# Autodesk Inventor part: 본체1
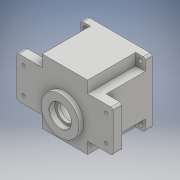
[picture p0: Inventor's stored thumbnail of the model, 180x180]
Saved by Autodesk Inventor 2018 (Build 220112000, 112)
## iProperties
Created: 2020-07
Part Number: 본체1
Material: 일반
Document SubType Name: Modeling
Designer: Admin
Density: 1 g/cm^3
Appearance: 기본값
Author: Admin
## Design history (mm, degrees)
sketch "스케치1"
  geometry: L1 (0, -65.8)-(0, 65.8) reference; L2 (-98, 0)-(98, 0) reference; L3 (33, 47)-(-33, 47); L4 (-33, 47)-(-33, 30); L5 (-33, 30)-(-70, 30); L6 (-70, 30)-(-70, -30); L7 (-70, -30)-(-33, -30); L8 (-33, -30)-(-33, -47); L9 (-33, -47)-(33, -47); L10 (33, -47)-(33, -30); L11 (33, -30)-(70, -30); L12 (70, -30)-(70, 30); L13 (70, 30)-(33, 30); L14 (33, 47)-(33, 30); 1 further point
  constraints: 24 end point, 8 perpendicular, 7 point on line, 1 horizontal, 3 other
  dimensions: "d0" = 140 distance between parallel lines of L6 L12; "d1" = 60 distance between parallel lines of L7 L5; "d2" = 66 distance of L3.start L3.end; "d3" = 17 distance of L3.end L4.end; "d4" = 17 distance of L7.end L8.end
extrude "돌출1" new body sketch "스케치1" distance "d5" = 13; taper "d6" = 0 deg
sketch "스케치2"
  geometry: L1 (-33, -47)-(33, -47) reference; L2 (33, -47)-(33, -30) reference; L3 (33, -30)-(70, -30) reference; L4 (70, -30)-(70, 30) reference; L5 (70, 30)-(33, 30) reference; L6 (33, 30)-(33, 47) reference; L7 (33, 47)-(-33, 47) reference; L8 (-33, 47)-(-33, 30) reference; L9 (-33, 30)-(-70, 30) reference; L10 (-70, 30)-(-70, -30) reference; L11 (-70, -30)-(-33, -30) reference; L12 (-33, -30)-(-33, -47) reference; L13 (-47, -47)-(47, -47); L14 (47, -47)-(47, 47); L15 (47, 47)-(-47, 47); L16 (-47, 47)-(-47, -47); L17 (-47, -47)-(47, 47); L18 (47, -47)-(-47, 47); 1 further point
  constraints: 12 end point, 2 midpoint, 2 parallel, 1 horizontal, 1 perpendicular
  dimensions: "d7" = 94 distance of L14.end L15.end; "d8" = 94 distance of L13.end L14.end
extrude "돌출2" join sketch "스케치2" distance "d9" = 67; taper "d10" = 0 deg
sketch "스케치3"
  geometry: L1 (-33, 47)-(33, 47) reference; L2 (-33, 30)-(-33, 47) reference; L3 (-70, 30)-(-33, 30) reference; L4 (-70, -30)-(-70, 30) reference; L5 (-33, -30)-(-70, -30) reference; L6 (-33, -47)-(-33, -30) reference; L7 (33, -47)-(-33, -47) reference; L8 (33, -30)-(33, -47) reference; L9 (70, -30)-(33, -30) reference; L10 (70, 30)-(70, -30) reference; L11 (33, 30)-(70, 30) reference; L12 (33, 47)-(33, 30) reference; L13 (33, 47)-(47, 47) reference; L14 (47, 47)-(47, 30) reference; L15 (47, -30)-(47, -47) reference; L16 (47, -47)-(33, -47) reference; L17 (-33, -47)-(-47, -47) reference; L18 (-47, -47)-(-47, -30) reference; L19 (-47, 30)-(-47, 47) reference; L20 (-47, 47)-(-33, 47) reference; L21 (47, -47)-(-47, -47) reference; L22 (-47, -47)-(-33, -47); L23 (-33, -47)-(-33, -30); L24 (-33, -30)-(-47, -30); L25 (-47, -30)-(-47, -47); L26 (-47, 30)-(-33, 30) reference; L27 (-47, 30)-(-33, 30); L28 (-33, 30)-(-33, 47); L29 (-33, 47)-(-47, 47); L30 (-47, 47)-(-47, 30); L31 (33, 47)-(33, 30) reference; L32 (33, 30)-(47, 30); L33 (47, 30)-(47, 47); L34 (47, 47)-(33, 47); L35 (33, 47)-(33, 30); L36 (33, -47)-(-33, -47) reference; L37 (33, -47)-(47, -47); L38 (47, -47)-(47, -30); L39 (47, -30)-(33, -30); L40 (33, -30)-(33, -47); 1 further point
  constraints: 32 end point, 8 parallel, 4 horizontal, 4 perpendicular
extrude "돌출3" cut sketch "스케치3" distance "d11" = 70; taper "d12" = 0 deg
sketch "스케치8"
  geometry: L1 (98, 0)-(-98, 0) reference; L2 (0, 65.8)-(0, -65.8) reference; C1 r 43 at (0, 0); 1 further point
  constraints: 1 centre point, 1 coincident
  dimensions: "d28" = 86 diameter of C1
extrude "돌출8" cut sketch "스케치8" distance "d29" = 9; taper "d30" = 0 deg
sketch "스케치9"
  geometry: C1 r 43 at (0, 0) reference; C2 r 40 at (0, 0); 1 further point
  constraints: 1 centre point, 1 coincident
  dimensions: "d31" = 80 diameter of C2
extrude "돌출9" cut sketch "스케치9" distance "d32" = 55; taper "d33" = 0 deg
sketch "스케치13"
  geometry: L1 (0, 65.8)-(0, -65.8) reference; L2 (98, 0)-(-98, 0) reference; L3 (-35.778, 3.994)-(-39.8, 3.994); L4 (-35.778, -3.994)-(-39.8, -3.994); C1 r 40 at (0, 0) reference; C2 r 43 at (0, 0) reference; A1 r 40 centre (0, 0) between (-39.8, 3.994) and (-39.8, -3.994) reference; A2 r 36 centre (0, 0) between (-36, 0) and (-35.778, 3.994); A3 r 4 centre (-36, 0) between (-36.222, -3.994) and (-36.222, 3.994); A4 r 40 centre (0, 0) between (-39.8, 3.994) and (-39.8, -3.994); 1 further point
  constraints: 11 point on circle, 4 end point, 3 centre point, 3 point on line, 2 coincident, 2 horizontal
  dimensions: "d45" = 72 diameter of A2; "d46" = 8 diameter of A3
extrude "돌출13" join sketch "스케치13" stored distance "d47" = 7; taper "d48" = 0 deg
sketch "스케치14"
  geometry: L1 (0, 65.8)-(0, -65.8) reference; L2 (98, 0)-(-98, 0) reference; L3 (-35.778, 3.994)-(-39.8, 3.994) reference; L4 (-39.8, -3.994)-(-35.778, -3.994) reference; C1 r 43 at (0, 0) reference; A1 r 40 centre (0, 0) between (-39.8, -3.994) and (-39.8, 3.994) reference; A2 r 4 centre (-36, 0) between (-35.778, -3.994) and (-35.778, 3.994) reference; 2 further points
  constraints: 1 coincident
hole "구멍1" sketch "스케치14" at (-36, 0) diameter "d49" = 3.242; stored, may be unused: countersink angle "d53" = 90 deg, drill point angle "d55" = 118 deg; dims "d50" = 7, "d51" = 4, "d52" = 2, "d54" = 9
sketch "스케치24"
  geometry: L1 (0, 65.8)-(0, -65.8) reference; L2 (98, 0)-(-98, 0) reference; L3 (70, -30)-(70, 30) reference; C1 r 5 at (60, -19); C2 r 5 at (60, 19); C3 r 5 at (-60, -19); C4 r 5 at (-60, 19); 5 further points
  constraints: 4 centre point, 4 symmetric about line, 2 coincident, 2 other
  dimensions: "d67" = 38 distance of point (60, -19) point (60, 19); "d68" = 10 distance from line of L3 point (60, -19); "d69" = 10 distance from line of L3 point (60, 19); "d70" = 19 distance from line of L2 point (60, -19); "d71" = 10 diameter of C1; "d72" = 10 diameter of C2
extrude "돌출17" cut sketch "스케치24" distance "d73" = 5; taper "d74" = 0 deg
sketch "스케치25"
  geometry: L1 (60, 84.8)-(60, -46.8) reference; C1 r 5 at (120, 0) reference; C2 r 5 at (120, 38) reference; C3 r 5 at (0, 38) reference; C4 r 5 at (0, 0) reference; C5 r 2.25 at (120, 0); C6 r 2.25 at (120, 38); C7 r 2.25 at (0, 0); C8 r 2.25 at (0, 38); 1 further point
  constraints: 4 centre point, 2 coincident, 2 symmetric about line, 2 other
  dimensions: "d75" = 4.5 diameter of C5; "d76" = 4.5 diameter of C6
extrude "돌출18" cut sketch "스케치25" extent not by distance; stored distance "d77" = 0; taper "d78" = 0 deg
sketch "스케치26"
  geometry: L1 (-98, 0)-(98, 0) reference; L2 (0, 65.8)-(0, -65.8) reference; L3 (-47, 47)-(47, 47) reference; L4 (47, 47)-(47, -47) reference; L5 (47, -47)-(-47, -47) reference; L6 (-47, -47)-(-47, 47) reference; L7 (40, -40)-(-40, -40); L8 (-40, -40)-(-40, 40); L9 (-40, 40)-(40, 40); L10 (40, 40)-(40, -40); L11 (40, -40)-(-40, 40); L12 (-40, -40)-(40, 40); C1 r 43 at (0, 0) reference; C2 r 3.5 at (40, -40); C3 r 3.5 at (40, 40); C4 r 3.5 at (-40, -40); C5 r 3.5 at (-40, 40); 1 further point
  constraints: 12 end point, 4 centre point, 3 symmetric about line, 2 midpoint, 2 parallel, 1 coincident, 1 horizontal, 1 perpendicular, 3 other
  dimensions: "d79" = 80 distance of L7.end L8.end; "d80" = 80 distance of L8.end L9.end; "d81" = 7 diameter of C2
extrude "돌출19" cut sketch "스케치26" extent not by distance; stored distance "d82" = 5; taper "d83" = 0 deg
sketch "스케치27"
  geometry: L1 (-14, 80)-(80, 80) reference; 2 further points
  constraints: 1 other
  dimensions: "d84" = 40 distance from line of L1 point (32.773, 40)
feature "엠보싱1" sketch "스케치27" dims "d0" = 140, "d1" = 60, "d2" = 66, "d3" = 17, "d4" = 17, "d85" = 0.5, "d86" = 0
fillet "모깎기1" dims "d87" = 3
chamfer "모따기1" distance "d89" = 1; stored, may be unused: second distance "d90" = 2, angle "d91" = 45 deg
sketch "스케치28"
  geometry: L1 (35.778, 3.994)-(39.8, 3.994) reference; L2 (-39.8, 3.994)-(-35.778, 3.994) reference; L3 (-35.778, -3.994)-(-39.8, -3.994) reference; L4 (39.8, -3.994)-(35.778, -3.994) reference; L5 (0, 65.8)-(0, -65.8) reference; L6 (98, 0)-(-98, 0) reference; C1 r 11 at (0, -20); A1 r 40 centre (0, 0) between (39.8, 3.994) and (-39.8, 3.994) reference; A2 r 4 centre (-36, 0) between (-35.778, -3.994) and (-35.778, 3.994) reference; A3 r 40 centre (0, 0) between (-39.8, -3.994) and (39.8, -3.994) reference; A4 r 4 centre (36, 0) between (35.778, 3.994) and (35.778, -3.994) reference; 1 further point
  constraints: 1 centre point, 1 point on line
  dimensions: "d98" = 22 diameter of C1; "d99" = 20 distance from line of C1.centre L6
extrude "돌출20" cut sketch "스케치28" distance "d100" = 7; taper "d101" = 0 deg
sketch "스케치29"
  geometry: L1 (0, 65.8)-(0, -65.8) reference; L2 (-98, 0)-(98, 0) reference; C1 r 27.5 at (0, -11); 1 further point
  constraints: 1 centre point, 1 point on line
  dimensions: "d104" = 55 diameter of C1; "d105" = 11 distance from line of L2 C1.centre
extrude "돌출21" join sketch "스케치29" distance "d106" = 7; taper "d107" = 0 deg
sketch "스케치30"
  geometry: C1 r 11 at (0, 0) reference; C2 r 9.5 at (0, 0); 1 further point
  constraints: 1 centre point, 1 coincident
  dimensions: "d108" = 19 diameter of C2
extrude "돌출22" cut sketch "스케치30" distance "d109" = 3; taper "d110" = 0 deg
sketch "스케치32"
  geometry: C1 r 27.5 at (0, 0) reference; C2 r 16 at (0, 0); 1 further point
  constraints: 1 centre point, 1 coincident
  dimensions: "d111" = 32 diameter of C2
extrude "돌출23" cut sketch "스케치32" distance "d112" = 8.3; taper "d113" = 0 deg
sketch "스케치33"
  geometry: C1 r 16 at (0, 0) reference; C2 r 12.5 at (0, 0); 1 further point
  constraints: 1 centre point, 1 coincident
  dimensions: "d114" = 25 diameter of C2
extrude "돌출24" cut sketch "스케치33" distance "d115" = 4.7; taper "d116" = 0 deg
sketch "스케치34"
  geometry: C1 r 12.5 at (0, 0) reference; C2 r 17.5 at (0, 0); 1 further point
  constraints: 1 centre point, 1 coincident
  dimensions: "d117" = 35 diameter of C2
extrude "돌출25" cut sketch "스케치34" distance "d118" = 10; taper "d119" = 0 deg
chamfer "모따기4" distance "d120" = 0.8; stored, may be unused: second distance "d121" = 2, angle "d122" = 30 deg
fillet "모깎기3" dims "d126" = 3
sketch "스케치36"
  geometry: L1 (35.778, 3.994)-(39.8, 3.994) reference; L2 (-39.8, 3.994)-(-35.778, 3.994) reference; L3 (-35.778, -3.994)-(-39.8, -3.994) reference; L4 (39.8, -3.994)-(35.778, -3.994) reference; C1 r 17.5 at (0, 11) reference; C2 r 11 at (0, -20) reference; A1 r 40 centre (0, 0) between (39.8, 3.994) and (-39.8, 3.994) reference; A2 r 4 centre (-36, 0) between (-35.778, -3.994) and (-35.778, 3.994) reference; A3 r 40 centre (0, 0) between (-39.8, -3.994) and (39.8, -3.994) reference; A4 r 4 centre (36, 0) between (35.778, 3.994) and (35.778, -3.994) reference; A5 r 21 centre (0, 11) between (8.978, -7.984) and (-8.978, -7.984); A6 r 15 centre (0, -20) between (-8.978, -7.984) and (8.978, -7.984); 1 further point
  constraints: 4 point on circle, 2 centre point, 2 coincident
  dimensions: "d129" = 42 diameter of A5; "d130" = 30 diameter of A6
extrude "돌출26" join sketch "스케치36" distance "d131" = 7; taper "d132" = 0 deg
chamfer "모따기6" distance "d133" = 1; stored, may be unused: second distance "d134" = 2, angle "d135" = 45 deg
node "솔리드1"
mirror "미러1"
node "투영된 루프1"
node "투영된 루프2"
node "투영된 루프10"
node "투영된 루프11"
node "투영된 루프15"
node "투영된 루프16"
node "투영된 루프17"
node "투영된 루프19"
node "투영된 루프20"
node "투영된 루프21"
node "투영된 루프23"
other parameters: "d127" = 42
